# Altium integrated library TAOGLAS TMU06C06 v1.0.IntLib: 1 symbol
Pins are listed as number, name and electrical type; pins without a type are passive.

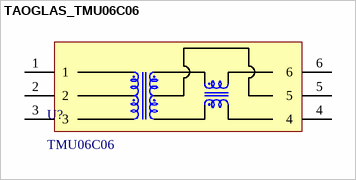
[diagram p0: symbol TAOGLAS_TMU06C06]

## TAOGLAS_TMU06C06
designator U?, comment TMU06C06
Transformer with Common Mode Choke for Battery Management System 6 pin SMT; ComponentLibStatus: Created; MFG: Taoglas; Temp_High: +85C; Temp_Low: -40C
footprint TAOGLAS_TMU06C06 (Transformer with Common Mode Choke for Battery Management System 6 pin SMT)
pins: 1, 2, 3, 4, 5, 6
